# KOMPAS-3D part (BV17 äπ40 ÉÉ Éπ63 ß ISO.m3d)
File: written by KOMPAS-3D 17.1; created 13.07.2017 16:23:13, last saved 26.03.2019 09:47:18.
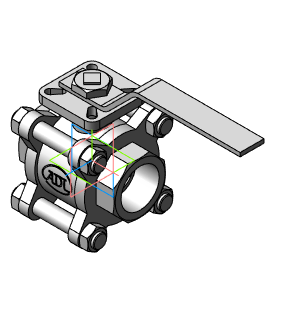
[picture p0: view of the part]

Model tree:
1. Операция без истории:3  (labels: Сталь 20  ГОСТ 1050-88)

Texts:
  DISO1
  DISO2
  BV17 Ду8 1/4" Ру63 с ISO
  BV17 Ду8 СС Ру63 с ISO
  BV17 Ду10 3/8" Ру63 с ISO
  BV17 Ду10 СС Ру63 с ISO
  BV17 Ду15 1/2" Ру63 с ISO
  BV17 Ду15 СС Ру63 с ISO
  BV17 Ду15 ФФ Ру40 с ISO
  BV17 Ду20 3/4" Ру63 с ISO
  BV17 Ду20 СС Ру40 с ISO
  BV17 Ду20 ФФ Ру40 с ISO
  BV17 Ду25 1" Ру63 с ISO
  BV17 Ду25 СС Ру63 с ISO
  BV17 Ду25 ФФ Ру40 с ISO
  BV17 Ду32 1 1/4" Ру63 с ISO
  BV17 Ду32 СС Ру63 с ISO
  BV17 Ду32 ФФ Ру40 с ISO
  BV17 Ду40 1 1/2" Ру63 с ISO
  BV17 Ду40 СС Ру63 с ISO
  BV17 Ду40 ФФ Ру40 с ISO
  BV17 Ду50 2" Ру63 с ISO
  BV17 Ду50 СС Ру63 с ISO
  BV17 Ду50 ФФ Ру40 с ISO
  BV17 Ду65 2 1/2" Ру40 с ISO
  BV17 Ду65 СС Ру40 с ISO
  BV17 Ду65 ФФ Ру40 с ISO
  BV17 Ду80 3" Ру40 с ISO
  BV17 Ду80 СС Ру40 с ISO
  BV17 Ду80 ФФ Ру40 с ISO
  BV17 Ду100 4" Ру40 с ISO
  BV17 Ду100 СС Ру40 с ISO
  BV17 Ду100 ФФ Ру40 с ISO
